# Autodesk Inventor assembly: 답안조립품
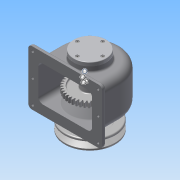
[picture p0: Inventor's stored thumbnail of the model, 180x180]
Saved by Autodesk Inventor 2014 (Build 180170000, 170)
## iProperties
Created: 2015-09
Part Number: 답안조립품
Document SubType Name: Assembly
Designer: imci
Author: imci
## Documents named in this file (14)
- C:\Users\imci\Desktop\450908V1006\답안조립품.iam
- C:\Users\imci\Desktop\450908V1006\본체(450908V1006).ipt
- C:\Users\imci\Desktop\450908V1006\V-벨트풀리.ipt
- C:\Users\imci\Desktop\450908V1006\뒤커버.ipt
- C:\Users\imci\Desktop\450908V1006\멈춤나사 - M4x10.ipt
- C:\Users\imci\Desktop\450908V1006\베어링 6203.ipt
- C:\Users\imci\Desktop\450908V1006\볼트 M3 x 8.ipt
- C:\Users\imci\Desktop\450908V1006\볼트 M3 x 10.ipt
- C:\Users\imci\Desktop\450908V1006\스퍼기어.ipt
- C:\Users\imci\Desktop\450908V1006\앞커버.ipt
- C:\Users\imci\Desktop\450908V1006\오일 실 17 32 8.ipt
- C:\Users\imci\Desktop\450908V1006\축.ipt
- C:\Users\imci\Desktop\450908V1006\키 - 5 x 5 x 18.ipt
- C:\Users\imci\Desktop\450908V1006\키 - 6 x 6 x 22.ipt
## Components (9 placed, 3 different names)
1. V-벨트풀리:1
2. ISO 4762 M3 x 10:1
3. ISO 4762 M3 x 10:2
4. ISO 4762 M3 x 10:3
5. ISO 4762 M3 x 10:4
6. ISO 4762 M3 x 8:1
7. ISO 4762 M3 x 8:2
8. ISO 4762 M3 x 8:3
9. ISO 4762 M3 x 8:4
